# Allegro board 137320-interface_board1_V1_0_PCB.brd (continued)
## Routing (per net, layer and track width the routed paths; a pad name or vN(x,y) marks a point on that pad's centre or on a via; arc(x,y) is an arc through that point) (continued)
MAIN_UART_RX12: length 98.2
  TOP w0.152: R123.1 v1(117.98,30.48)
  ART03 w0.127: v1(117.98,30.48) 117.35,30.48 110.74,23.88 98.33,23.88 92.87,18.41 86.74,18.41 82.3,13.97 70.99,13.97 70.74,13.72 61.21,13.72 58.55,11.05 53.34,11.05 52.45,10.16 52.45,6.6 51.18,5.33 48.9,5.33 48,4.44 48,1.64 47.37,1.02 37.98,1.02 J4.15
MAIN_UART_RX13: length 130.6
  ART03 w0.127: J4.18 42.24,7.24 46.35,7.24 47.24,8.13 49.66,8.13 50.55,9.02 50.55,10.79 52.7,12.95 57.91,12.95 61.47,16.51 70.1,16.51 70.74,15.88 81.66,15.88 87.5,21.72 93.48,21.72 97.54,25.78 110.11,25.78 115.32,30.99 115.32,57.66 117.47,59.82 117.47,69.98 v1(117.98,70.48)
  BOTTOM w0.152: R128.1 v1(117.98,70.48)
MAIN_UART_RX14: length 108
  TOP w0.152: R133.1 v1(116.46,45.09)
  ART03 w0.127: J4.19 40,3 40,4.44 42.42,6.86 46.61,6.86 47.5,7.75 49.78,7.75 50.93,8.89 50.93,10.67 52.83,12.57 58.04,12.57 61.59,16.13 69.98,16.13 70.61,15.49 81.79,15.49 87.63,21.34 93.64,21.34 97.7,25.4 110.24,25.4 115.7,30.86 115.7,44.32 v1(116.46,45.09)
MAIN_UART_RX15: length 120.7
  TOP w0.152: R138.1 v1(117.98,59.69)
  ART03 w0.127: J4.21 42,3 42,4.41 43.69,6.1 50.8,6.1 51.69,6.99 51.69,10.41 53.09,11.81 58.29,11.81 60.96,14.48 70.23,14.48 70.48,14.73 82.04,14.73 86.49,19.18 92.56,19.18 98.02,24.64 110.49,24.64 116.46,30.61 116.46,35.18 116.97,35.69 116.97,58.67 v1(117.98,59.69)
MAIN_UART_RX16: length 91.4
  TOP w0.152: 108.58,40.77 v1(108.58,39.88)
  ART03 w0.127: v1(59.44,17.78) 59.69,18.03 67.31,18.03 71.75,22.48 80.52,22.48 85.34,27.3 90.81,27.3 91.19,27.69 106.3,27.69 108.58,29.97 v1(108.58,39.88)
  ART04 w0.127: v1(59.44,17.78) 60.07,17.14 60.07,9.65 56.39,5.97 53.59,5.97 52,4.37 52,3.61 51.39,3 50.62,3 50,2.37 50,1.49 49.53,1.02 47.98,1.02 J4.25
MAIN_UART_RX17: length 94.3
  TOP w0.152: R207.1 v1(107.31,55.75)
  ART03 w0.127: v1(107.31,55.75) 100.71,49.15 93.95,49.15 89.5,44.7 87.38,44.7 85.22,42.55 85.22,30.13 78.33,23.24 71.5,23.24 67.94,19.68 60.07,19.68 v1(58.17,17.78)
  ART04 w0.127: v1(58.17,17.78) 58.8,17.14 58.8,9.4 56.13,6.73 51.94,6.73 50.93,5.71 49.78,5.71 49,4.93 J4.28
MAIN_UART_RX18: length 82.2
  ART03 w0.127: J4.29 52,3 52,4.37 52.58,4.95 55.88,4.95 56.77,5.84 60.58,5.84 64.26,9.53 93.64,9.53 97.2,5.97 103.63,5.97 104.52,5.08 125.92,5.08 J6.30
MAIN_UART_RX19: length 80.8
  TOP w0.152: R40.1 v1(83.19,53.21)
  ART03 w0.127: J4.31 54,3 55.44,3 56,3.56 56,4.44 56.64,5.08 62.1,5.08 65.41,8.38 83.57,8.38 v1(83.69,8.26)
  ART04 w0.127: v1(83.69,8.26) 84.33,8.89 84.33,11.3 83.57,12.06 83.57,34.29 82.8,35.05 82.8,52.83 v1(83.19,53.21)
MAIN_UART_TX0_DEBUG: length 74.4
  TOP w0.152: v1(87.12,79.5) 87.12,75.69 90.81,72.01 90.81,65.91 87,62.1 84.71,62.1 83.86,61.25 U41.11
  ART03 w0.127: J3.20 43,87 43,85.65 44.2,84.45 60.23,84.45 64.67,80.01 86.61,80.01 v1(87.12,79.5)
MAIN_UART_TX1: length 56
  TOP w0.152: U11.5 v1(33.02,41.53)
  ART04 w0.127: J3.21 45,87 46.6,87 47,86.6 47,85.23 46.74,84.96 46.74,65.53 33.66,52.45 33.66,42.16 v1(33.02,41.53)
MAIN_UART_TX2: length 61.5
  TOP w0.152: U13.5 v1(43.18,41.53)
  ART04 w0.127: J3.24 46.49,88 47.5,87 54.48,87 55,86.48 55,85.35 53.91,84.27 53.91,72.46 50.87,69.41 50.87,59.76 42.55,51.44 42.55,42.16 v1(43.18,41.53)
MAIN_UART_TX3: length 50.1
  TOP w0.152: U15.5 v1(53.34,41.53)
  ART04 w0.127: v1(55.5,80.9) 55.5,72.01 52.7,69.22 52.7,42.16 v1(53.34,41.53)
  BOTTOM w0.152: v1(55.5,80.9) 53.85,82.55 53.09,82.55 50,85.64 J3.27
MAIN_UART_TX4: length 70.6
  TOP w0.152: U17.5 v1(33.02,25.65)
  ART04 w0.127: v1(33.02,25.65) 33.66,26.29 33.66,39.75 34.92,41.02 34.92,53.21 47.1,65.38 47.1,82.66 48.26,83.82 49.82,83.82 J3.29
MAIN_UART_TX5: length 67.2
  TOP w0.152: U19.5 v1(43.18,25.65)
  ART04 w0.127: v1(43.18,25.65) 43.81,26.29 43.81,52.2 51.22,59.61 51.22,69.26 54.27,72.31 54.27,83.1 56,84.83 J3.33
MAIN_UART_TX6: length 66.6
  TOP w0.152: U21.5 v1(53.34,25.65)
  ART04 w0.127: J3.36 59,87 59,80.59 55.88,77.47 55.88,71.88 53.98,69.98 53.98,26.29 v1(53.34,25.65)
MAIN_UART_TX7: length 104.2
  TOP w0.152: U23.5 v1(33.02,9.78)
  ART04 w0.127: v1(33.02,9.78) 33.66,9.14 42.29,9.14 43.94,10.79 50.55,10.79 52.32,9.02 54.86,9.02 55.24,9.4 55.24,60.83 58.17,63.75 58.17,70.48 60,72.32 J3.37
MAIN_UART_TX8: length 95
  TOP w0.152: v1(44.45,8.51) 43.18,9.78 U25.5
  ART04 w0.127: J3.39 60.58,84.58 60.58,72.39 59.05,70.87 59.05,58.17 56.9,56.01 56.9,9.53 55.63,8.26 44.7,8.26 v1(44.45,8.51)
MAIN_UART_TX9: length 32.8
  TOP w0.152: J4.6 28,3 29.54,3 30,3.46 30,4.35 30.86,5.21 49.91,5.21 53.98,9.27 53.98,10.16 53.34,10.79 U27.5
MAIN_UART_TX10: length 89.7
  TOP w0.152: U47.5 v1(113.67,9.91)
  ART03 w0.127: v1(59.18,8) 59.82,8.64 60.74,8.64 63.53,11.43 72.68,11.43 73.69,12.45 93.99,12.45 96.89,9.55 107.58,9.55 108.32,8.81 112.57,8.81 v1(113.67,9.91)
  BOTTOM w0.152: J4.10 31,4.33 32.51,5.84 57.02,5.84 v1(59.18,8)
MAIN_UART_TX11: length 100.1
  TOP w0.152: U49.5 v1(124.46,9.91)
  ART03 w0.127: v1(60.33,8) 60.64,8 63.69,11.05 72.84,11.05 73.85,12.06 93.91,12.06 96.75,9.22 107.45,9.22 108.31,8.36 122.91,8.36 v1(124.46,9.91)
  BOTTOM w0.152: J4.12 34.08,5.08 59.44,5.08 60.96,6.6 60.96,7.37 v1(60.33,8)
MAIN_UART_TX12: length 106.3
  TOP w0.152: U33.7 v1(124.33,26.67)
  ART03 w0.127: J4.13 36.36,0.64 49.15,0.64 50,1.49 50,4.53 50.42,4.95 51.44,4.95 52.83,6.35 52.83,10.03 53.47,10.67 58.67,10.67 61.34,13.34 70.99,13.34 71.25,13.59 82.42,13.59 86.87,18.03 92.96,18.03 98.42,23.5 121.41,23.5 124.33,26.42 v1(124.33,26.67)
MAIN_UART_TX13: length 146.1
  ART03 w0.127: J4.16 38.73,5.74 38.73,6.99 39.37,7.62 46.1,7.62 46.99,8.51 49.53,8.51 50.16,9.14 50.16,10.92 52.58,13.34 57.66,13.34 61.21,16.89 69.85,16.89 70.36,17.4 78.23,17.4 79.01,18.17 83.45,18.17 87.38,22.1 93.32,22.1 97.38,26.16 109.98,26.16 114.94,31.11 114.94,57.91 117.09,60.07 117.09,75.56 117.73,76.2 122.43,76.2 v1(124.33,74.3)
  BOTTOM w0.152: U35.7 v1(124.33,74.3)
MAIN_UART_TX14: length 108.4
  TOP w0.152: v1(116.46,36.2) 124.08,36.2 124.97,37.08 124.97,40.77 124.46,41.27 U37.7
  ART03 w0.127: J4.20 43.48,6.48 46.86,6.48 47.75,7.37 50.04,7.37 51.31,8.64 51.31,10.54 52.96,12.19 58.17,12.19 61.72,15.75 69.85,15.75 70.48,15.11 81.92,15.11 87.76,20.95 93.79,20.95 97.86,25.02 110.36,25.02 116.08,30.73 116.08,35.81 v1(116.46,36.2)
MAIN_UART_TX15: length 121
  TOP w0.152: U39.7 124.33,55.88 124.97,55.24 124.97,51.56 124.21,50.8 v1(117.98,50.8)
  ART03 w0.127: v1(117.98,50.8) 117.35,50.16 117.35,35.56 116.84,35.05 116.84,30.48 110.62,24.26 98.17,24.26 92.71,18.8 86.61,18.8 82.17,14.35 70.74,14.35 70.48,14.1 61.09,14.1 58.42,11.43 53.21,11.43 52.07,10.29 52.07,6.86 50.93,5.71 44.71,5.71 J4.22
MAIN_UART_TX16: length 87.6
  TOP w0.152: Q3.1 v1(110.8,33.66)
  ART03 w0.127: v1(59.44,16.51) 60.58,17.65 68.58,17.65 73.03,22.1 80.64,22.1 85.47,26.92 91.06,26.92 91.44,27.3 107.57,27.3 110.8,30.54 v1(110.8,33.66)
  ART04 w0.127: J4.23 46,3 49.35,3 50,3.64 50,4.79 50.55,5.33 51.05,5.33 52.07,6.35 56.26,6.35 59.44,9.53 v1(59.44,16.51)
  BOTTOM w0.152: R190.2 111.25,33.21 v1(110.8,33.66)
MAIN_UART_TX17: length 96.8
  TOP w0.152: Q7.1 v1(110.8,49.53)
  ART03 w0.127: v1(110.8,49.53) 110.04,48.77 94.11,48.77 89.66,44.32 87.5,44.32 85.6,42.42 85.6,29.97 78.49,22.86 71.63,22.86 67.18,18.41 59.31,18.41 58.8,17.91 58.8,17.14 v1(58.17,16.51)
  ART04 w0.127: v1(58.17,16.51) 58.17,9.27 56.01,7.11 51.82,7.11 50.8,6.1 49.1,6.1 J4.26
  BOTTOM w0.152: R198.2 111.25,49.08 v1(110.8,49.53)
MAIN_UART_TX18: length 84.6
  ART03 w0.127: J4.30 52.33,5.33 55.63,5.33 56.52,6.22 60.45,6.22 64.14,9.91 93.73,9.91 97.29,6.35 103.89,6.35 104.78,5.46 127,5.46 128,4.46 128,3 J6.29
MAIN_UART_TX19: length 65.5
  TOP w0.152: U6.52 82.26,46.74 82.01,46.48 v1(81.03,46.48)
  ART04 w0.127: v1(81.03,46.48) 79.76,45.21 79.76,29.21 80.39,28.57 80.39,24.51 77.47,21.59 77.47,13.97 72.26,8.76 65.28,8.76 61.85,5.33 54.33,5.33 J4.32
MAIN_USB_DN: length 68.9
  TOP w0.15: L8.2 19.28,66.95 19.55,66.69 19.55,21.59 21.44,19.7 21.44,14.33 21.21,14.1 21.21,13.74 21.44,13.5 21.44,13.14 21.21,12.9 21.21,12.54 21.44,12.31 21.44,11.94 21.21,11.71 21.21,11.34 21.44,11.11 21.44,10.74 21.21,10.51 21.21,10.14 21.44,9.91 21.44,9.54 21.21,9.31 21.21,8.94 21.44,8.71 21.44,8.34 21.21,8.11 21.21,7.74 21.44,7.51 21.44,7.14 21.21,6.91 21.21,6.54 21.44,6.31 21.44,5.94 21.21,5.71 21.21,5.34 21.44,5.11 21.44,4.74 21.21,4.51 21.21,4.14 21.44,3.91 21.44,3.56 J4.1
MAIN_USB_DP: length 68.8
  TOP w0.15: J4.3 24,3 22.39,3 21.72,3.67 21.72,19.81 19.82,21.71 19.82,66.69 20.09,66.95 L8.3
MAIN_USB_VBUS: length 99.1
  TOP w0.508: 54.36,66.67 53.34,66.67 47.88,72.14 35.94,72.14 34.92,71.12 26.54,71.12 23,67.58 J4.2
MAIN_USB_VBUS_EN_N: length 89.6
  ART04 w0.127: v1(57.15,60.33) 56.52,59.69 56.52,9.65 55.5,8.64 52.07,8.64 50.29,10.41 44.2,10.41 42.55,8.76 28.96,8.76 26,5.81 26,3 J4.5
  BOTTOM w0.152: R152.2 v1(57.15,60.33)
NC2: length 230.3
  TOP w0.152: v1(96.27,14.22) 91.69,18.8 84.96,18.8 v1(84.07,19.68) ; v1(39.37,15.24) 38.73,14.61 29.84,14.61 v1(29.21,15.24) ; U7.13 v1(134.62,14.22)
  ART03 w0.127: v1(96.27,14.22) 96.38,14.22 96.51,14.1 108.58,14.1 v1(109.86,12.83) 110.35,13.32 120.15,13.32 v1(120.65,12.83) 121.67,11.81 130.68,11.81 131.43,12.56 132.96,12.56 v1(134.62,14.22) ; v1(49.53,15.24) 50.16,15.88 59.69,15.88 61.09,17.27 69.72,17.27 70.98,18.53 82.92,18.53 v1(84.07,19.68) ; v1(49.53,44.45) v1(39.37,44.45)
  ART04 w0.127: v1(29.21,44.45) 30.73,42.93 30.73,39.62 29.84,38.73 29.84,29.21 v1(29.21,28.57) 30.61,27.18 30.61,23.75 29.84,22.99 29.84,15.88 v1(29.21,15.24) ; v1(39.37,15.24) 40.01,15.88 40.01,27.94 v1(39.37,28.57) 40.01,29.21 40.01,43.81 v1(39.37,44.45) ; v1(49.53,15.24) 50.16,15.88 50.16,27.94 v1(49.53,28.57) 50.16,29.21 50.16,43.81 v1(49.53,44.45)
  BOTTOM w0.152: 109.86,11.3 v1(109.86,12.83) ; U16.13 v1(49.53,44.45) ; U50.13 v1(120.65,12.83) ; U18.13 v1(29.21,28.57) ; U14.13 v1(39.37,44.45) ; U22.13 v1(49.53,28.57) ; U12.13 v1(29.21,44.45) ; U26.13 v1(39.37,15.24) ; U24.13 v1(29.21,15.24) ; U20.13 v1(39.37,28.57) ; U28.13 v1(49.53,15.24)
RS485_DRIVE_EN: length 88.1
  TOP w0.152: U7.4 v1(137.16,9.91) ; v1(87.12,41.53) 86.74,41.91 U6.40
  ART03 w0.127: v1(137.16,9.91) 135.28,8.03 108.17,8.03 107.31,8.89 99.44,8.89 v1(98.93,8.38)
  ART04 w0.127: v1(87.12,41.53) 84.96,39.37 84.96,14.48 90.81,8.64 98.68,8.64 v1(98.93,8.38)
  BOTTOM w0.152: v1(137.16,9.91) R49.1
RX_DEBUG_MAIN: length 77.5
  TOP w0.152: J1.41 10.99,66.09 12.64,64.45 D49.2 v1(15.88,64.45) ; v1(75.69,59.69) 75.96,59.95 U41.8
  ART03 w0.127: v1(75.69,59.69) 75.18,60.2 60.33,60.2 57.66,62.87 36.96,62.87 36.07,61.98 36.07,60.71 33.02,57.66 22.67,57.66 v1(15.88,64.45)
RX_DEBUG_SPARE: length 81.7
  TOP w0.152: U42.8 92.45,14.87 92.71,14.61 93.85,14.61 v1(94.23,14.22) ; D50.2 v1(144.15,24.45)
  ART03 w0.127: v1(144.15,24.45) 144.65,23.94 144.65,19.43 140.98,15.76 137.62,15.76 136.23,17.14 121.4,17.14 120.76,16.51 99.19,16.51 97.41,14.73 94.74,14.73 v1(94.23,14.22)
  ART04 w0.127: v1(144.15,24.45) 152.47,24.45 156.34,28.32 156.34,31.89 J2.43
SPARE_ID2: length 81
  TOP w0.152: v1(87.12,38.99) 86.55,38.41 U6.33
  ART03 w0.127: v1(114.3,40.01) 113.28,41.02 103.38,41.02 101.35,38.99 v1(87.12,38.99)
  ART04 w0.127: J5.12 111,87 111,83.69 114.3,80.39 v1(114.3,40.01)
  BOTTOM w0.152: R37.2 87,39.12 v1(87.12,38.99)
SPARE_POWER_EN: length 48.3
  TOP w0.152: 34.92,61.09 36.7,61.09 37.08,61.47 v1(37.08,61.98) ; v1(78.11,58.55) 78.36,58.29 Q2.3
  ART03 w0.127: v1(78.11,58.55) 75.69,58.55 75.18,59.05 70.23,59.05 69.47,59.82 60.07,59.82 57.91,61.98 v1(37.08,61.98)
  BOTTOM w0.152: v1(37.08,61.98) 37.59,61.98 37.74,62.12 U3.5
SPARE_SAFE_MODE_EN_N: length 305.8
  TOP w0.152: U36.6 v1(124.33,71.75)
  ART03 w0.127: v1(31.75,18.16) 32.13,18.16 32.77,17.53 41.27,17.53 v1(41.91,18.16) ; v1(62.1,12.32) 62.74,12.95 71.25,12.95 71.5,13.21 82.55,13.21 84.45,15.11 94.87,15.11 96.01,16.26 97.28,16.26 98.3,17.27 111.63,17.27 v1(112.39,18.03) 113.16,17.27 120.59,17.27 121.35,18.03 v1(123.19,18.03) ; v1(41.91,49.91) 42.42,49.4 51.56,49.4 v1(52.07,49.91)
  ART04 w0.127: v1(123.19,18.03) 125.35,20.19 125.35,28.19 v1(124.33,29.21) 124.97,29.84 124.97,43.18 v1(124.33,43.81) 124.97,44.45 124.97,57.78 v1(124.33,58.42) 123.7,59.05 123.7,71.12 v1(124.33,71.75) 125.09,72.52 125.09,78.61 v1(124.33,79.38) ; v1(31.75,18.16) 31.11,18.8 31.11,33.4 v1(31.75,34.04) 31.11,34.67 31.11,49.28 v1(31.75,49.91) ; v1(41.91,18.16) 41.27,18.8 41.27,33.4 v1(41.91,34.04) 41.27,34.67 41.27,49.28 v1(41.91,49.91) ; v1(52.07,49.91) 51.44,49.28 51.44,34.67 v1(52.07,34.04) 51.44,33.4 51.44,18.8 v1(52.07,18.16)
  BOTTOM w0.152: U40.6 v1(124.33,58.42) ; v1(62.1,12.32) 62.1,16.97 59.77,19.3 53.21,19.3 v1(52.07,18.16) U28.4 ; U48.4 v1(112.39,18.03) ; U14.4 v1(41.91,49.91) ; U20.4 v1(41.91,34.04) ; U22.4 v1(52.07,34.04) ; U12.4 v1(31.75,49.91) ; U18.4 v1(31.75,34.04) ; U26.4 v1(41.91,18.16) ; U38.6 v1(124.33,43.81) ; U50.4 v1(123.19,18.03) ; U34.6 v1(124.33,29.21) ; v1(124.33,79.38) 121.92,79.38 120.65,78.11 R2.2 119.89,82.3 117.86,84.33 116.14,84.33 115,85.47 115,87 J5.16 ; U16.4 v1(52.07,49.91) ; U24.4 v1(31.75,18.16)
SPARE_UART_RX0_DEBUG: length 81.2
  TOP w0.152: R149.1 v1(92.08,26.16)
  ART03 w0.127: v1(92.08,26.16) 96.39,26.16 97.16,26.92 109.47,26.92 113.79,31.24 113.79,32 v1(114.43,32.64)
  ART04 w0.127: J5.19 115.57,83.57 115.57,61.09 114.81,60.33 114.81,33.02 v1(114.43,32.64)
SPARE_UART_RX1: length 116.9
  ART03 w0.127: v1(29.21,52.83) 31.75,55.37 58.42,55.37 62.48,59.44 69.25,59.44 70.01,58.67 74.71,58.67 75.72,57.66 81.79,57.66 82.8,58.67 84.71,58.67 90.17,64.14 90.17,65.66 90.81,66.29 90.81,69.34 91.95,70.48 91.95,77.22 96.2,81.47 102.17,81.47 105.66,84.96 118.36,84.96 119,85.6 119,86.49 119.51,87 121,87 J5.23
  BOTTOM w0.152: R64.1 v1(29.21,52.83)
SPARE_UART_RX2: length 108.3
  ART03 w0.127: J5.26 123.06,87.06 123.06,85.47 121.89,84.3 106.02,84.3 102.53,80.81 96.48,80.81 92.71,77.04 92.71,65.66 83.95,56.9 75.15,56.9 74.39,57.66 61.72,57.66 57.91,53.85 40.39,53.85 v1(39.37,52.83)
  BOTTOM w0.152: R70.1 v1(39.37,52.83)
SPARE_UART_RX3: length 102.1
  ART03 w0.127: J5.28 127,87 127,84.96 125.35,83.31 106.55,83.31 102.74,79.5 102.74,74.17 84.33,55.75 74.68,55.75 73.91,56.52 62.1,56.52 54.86,49.28 53.09,49.28 52.7,49.66 52.7,50.16 51.31,51.56 50.8,51.56 v1(49.53,52.83)
  BOTTOM w0.152: R76.1 v1(49.53,52.83)
SPARE_UART_RX4: length 134.3
  ART03 w0.127: v1(29.21,36.96) 31.11,35.05 31.11,33.91 31.62,33.4 33.15,33.4 33.66,33.91 33.66,34.54 37.08,37.97 53.21,37.97 56.64,41.4 56.64,47.24 60.83,51.44 65.15,51.44 66.67,52.96 70.99,52.96 72.14,54.1 76.58,54.1 77.47,54.99 84.58,54.99 103.5,73.91 103.5,79.25 106.91,82.65 126.21,82.65 129,85.44 129,87 J5.30
  BOTTOM w0.152: R82.1 v1(29.21,36.96)
SPARE_UART_RX5: length 118.4
  ART03 w0.127: J5.31 130,85.93 126.39,82.32 107.09,82.32 103.89,79.12 103.89,73.79 84.71,54.61 77.6,54.61 76.71,53.72 72.26,53.72 71.12,52.58 66.8,52.58 65.28,51.05 61.09,51.05 57.02,46.99 57.02,41.15 53.47,37.59 40.01,37.59 v1(39.37,36.96)
  BOTTOM w0.152: R88.1 v1(39.37,36.96)
SPARE_UART_RX6: length 112.3
  ART03 w0.127: J5.34 131,87 131,85.6 130.36,84.96 129.54,84.96 126.57,81.99 107.26,81.99 104.27,78.99 104.27,73.66 84.84,54.23 77.72,54.23 76.83,53.34 72.39,53.34 71.25,52.2 66.93,52.2 65.41,50.67 61.21,50.67 57.4,46.86 57.4,41.02 52.83,36.45 50.04,36.45 v1(49.53,36.96)
  BOTTOM w0.152: R94.1 v1(49.53,36.96)
SPARE_UART_RX7: length 154.2
  ART03 w0.127: v1(29.21,21.08) 30.23,22.1 53.21,22.1 56.52,25.4 56.52,38.61 58.55,40.64 58.55,46.48 61.59,49.53 65.79,49.53 67.31,51.05 71.68,51.05 72.83,52.2 84.33,52.2 93.47,61.34 110.62,61.34 113.16,63.88 113.16,66.67 115.57,69.09 115.57,77.98 116.87,79.27 122.33,79.27 123.95,80.9 127,80.9 129.92,83.82 133.22,83.82 135,85.6 135,87 J5.38
  BOTTOM w0.152: R100.1 v1(29.21,21.08)
SPARE_UART_RX8: length 146.9
  ART03 w0.127: J5.40 137,87 137,85.56 134.49,83.06 130.18,83.06 127.25,80.14 124.21,80.14 122.68,78.61 117.22,78.61 116.33,77.72 116.33,68.83 113.92,66.42 113.92,63.63 110.87,60.58 93.73,60.58 84.58,51.44 73.28,51.44 71.37,49.53 67.44,49.53 66.67,48.77 61.85,48.77 59.31,46.23 59.31,40.39 57.28,38.35 57.28,25.15 52.2,20.07 40.39,20.07 v1(39.37,21.08)
  BOTTOM w0.152: R106.1 v1(39.37,21.08)
SPARE_UART_RX9: length 71.6
  ART03 w0.127: v1(62.61,6.99) 64.77,9.14 93.56,9.14 97.11,5.59 103.41,5.59 J6.8
  BOTTOM w0.152: R112.1 50.16,20.83 50.16,21.34 50.55,21.72 58.17,21.72 62.61,17.27 v1(62.61,6.99)
SPARE_UART_RX10: length 22
  ART04 w0.127: J6.9 106,3 106,9.48 109.22,12.7 109.22,20.45 v1(109.86,21.08)
  BOTTOM w0.152: R168.1 v1(109.86,21.08)
SPARE_UART_RX11: length 25.5
  BOTTOM w0.152: J6.11 110,3 110,4.72 113.28,8 116.84,8 117.35,8.51 117.35,17.53 120.02,20.19 R173.1
SPARE_UART_RX12: length 28.8
  TOP w0.152: v1(116.84,8.89) 116.2,8.26 116.2,5.71 116,5.51 116,3.48 115.52,3 114,3 J6.15
  ART04 w0.127: v1(116.84,8.89) 117.86,9.91 117.86,20.7 117.47,21.08 117.47,26.16 v1(117.98,26.67)
  BOTTOM w0.152: R126.1 v1(117.98,26.67)
SPARE_UART_RX13: length 73.8
  TOP w0.152: J6.18 115,8.07 v1(115.82,8.89) ; R131.1 v1(117.98,74.3)
  ART04 w0.127: v1(117.98,74.3) 117.22,73.53 117.22,61.72 115.57,60.07 115.57,35.81 116.33,35.05 116.33,20.61 116.71,20.23 116.71,11.68 115.32,10.29 115.32,9.4 v1(115.82,8.89)
SPARE_UART_RX14: length 41.8
  TOP w0.152: v1(116.84,9.91) 117.35,9.4 117.35,7.49 118,6.84 118,3 J6.19
  ART04 w0.127: v1(117.98,41.27) 117.09,40.39 117.09,20.92 117.47,20.54 117.47,10.54 v1(116.84,9.91)
  BOTTOM w0.152: R136.1 v1(117.98,41.27)
SPARE_UART_RX15: length 66.3
  TOP w0.152: J6.21 118.02,1.02 112.52,1.02 112,1.54 112,4.56 113.67,6.22 113.67,7.75 v1(115.82,9.91)
  ART04 w0.127: v1(115.82,9.91) 115.82,10.16 117.09,11.43 117.09,20.39 116.71,20.77 116.71,35.18 115.95,35.94 115.95,53.85 v1(117.98,55.88)
  BOTTOM w0.152: R141.1 v1(117.98,55.88)
SPARE_UART_RX16: length 48.7
  TOP w0.152: 107.31,40.77 v1(107.31,39.88)
  ART04 w0.127: v1(107.31,39.88) 107.31,38.61 108.46,37.47 108.46,30.48 111.76,27.18 111.76,9.27 v1(114.3,6.73)
  BOTTOM w0.152: v1(114.3,6.73) 115.57,5.46 121.41,5.46 122,4.87 122,3 J6.25
SPARE_UART_RX17: length 65.3
  TOP w0.152: R206.1 v1(108.58,55.75)
  ART04 w0.127: v1(108.58,55.75) 112.27,55.75 113.67,54.36 113.67,39.62 113.92,39.37 113.92,22.48 115.57,20.83 115.57,11.43 114.94,10.79 114.94,8.64 v1(116.84,6.73)
  BOTTOM w0.152: J6.28 122.78,6.22 117.35,6.22 v1(116.84,6.73)
SPARE_UART_RX19: length 115.4
  TOP w0.152: v1(81.03,49.15) 80.76,48.88 U6.55 ; J9.5 v1(80.01,67.06)
  ART03 w0.127: v1(82.42,10.41) 82.93,10.92 93.65,10.92 97.46,7.11 104.39,7.11 105.28,6.22 128.14,6.22 130,4.37 130,3 J6.31
  ART04 w0.127: v1(80.01,67.06) 80.01,50.16 v1(81.03,49.15) 81.66,48.51 81.66,45.59 81.03,44.96 81.03,29.46 81.79,28.7 81.79,11.05 v1(82.42,10.41)
SPARE_UART_TX0_DEBUG: length 87.1
  TOP w0.152: U42.11 v1(91.15,22.61)
  ART03 w0.127: v1(91.15,22.61) 93.34,22.61 97.28,26.54 109.6,26.54 v1(114.43,31.37)
  ART04 w0.127: v1(114.43,31.37) 115.19,32.13 115.19,60.2 116.84,61.85 116.84,83.19 119,85.35 119,87 J5.20
SPARE_UART_TX1: length 111.6
  ART03 w0.127: v1(33.02,49.91) 37.34,54.23 57.78,54.23 62.61,59.05 69.09,59.05 69.85,58.29 74.55,58.29 75.56,57.28 83.82,57.28 90.55,64.01 90.55,65.53 92.33,67.31 92.33,77.13 96.34,81.14 102.35,81.14 105.84,84.63 118.63,84.63 J5.21
  BOTTOM w0.152: U12.5 v1(33.02,49.91)
SPARE_UART_TX2: length 112
  ART03 w0.127: v1(43.18,49.91) 46.74,53.47 58.04,53.47 61.85,57.28 74.23,57.28 74.99,56.52 84.07,56.52 93.09,65.53 93.09,76.96 96.61,80.48 102.7,80.48 106.2,83.97 123.6,83.97 124.97,85.34 124.97,88.39 124.33,89.03 123.03,89.03 J5.24
  BOTTOM w0.152: U14.5 v1(43.18,49.91)
SPARE_UART_TX3: length 93.5
  ART03 w0.127: v1(53.34,49.91) 56.52,53.09 58.17,53.09 61.98,56.9 74.07,56.9 74.83,56.13 84.2,56.13 102.36,74.3 102.36,79.63 106.38,83.64 124.66,83.64 126,84.98 J5.27
  BOTTOM w0.152: U16.5 v1(53.34,49.91)
SPARE_UART_TX4: length 125.8
  ART03 w0.127: v1(33.02,34.04) 33.02,34.92 37.34,39.24 53.21,39.24 55.24,41.27 55.24,47.24 59.82,51.82 65.02,51.82 66.55,53.34 69.98,53.34 72.01,55.37 84.45,55.37 103.12,74.04 103.12,79.38 106.73,82.98 126.03,82.98 128,84.95 J5.29
  BOTTOM w0.152: U18.5 v1(33.02,34.04)
SPARE_UART_TX5: length 118.4
  ART03 w0.127: J5.33 130.58,84.58 129.67,84.58 126.75,81.66 107.44,81.66 104.65,78.87 104.65,73.53 84.96,53.85 77.85,53.85 76.96,52.96 72.52,52.96 71.37,51.82 67.06,51.82 65.53,50.29 61.34,50.29 57.78,46.74 57.78,40.89 51.82,34.92 44.07,34.92 v1(43.18,34.04)
  BOTTOM w0.152: U20.5 v1(43.18,34.04)
SPARE_UART_TX6: length 116.7
  ART03 w0.127: J5.36 133,87 133,85.6 131.6,84.2 129.79,84.2 126.87,81.28 123.83,81.28 122.15,79.6 116.69,79.6 115.19,78.11 115.19,69.22 112.78,66.8 112.78,64.01 110.49,61.72 93.34,61.72 84.2,52.58 72.64,52.58 71.5,51.44 67.18,51.44 65.66,49.91 61.47,49.91 58.17,46.61 58.17,40.77 53.34,35.94 v1(53.34,34.04)
  BOTTOM w0.152: U22.5 v1(53.34,34.04)
SPARE_UART_TX7: length 151.1
  ART03 w0.127: J5.37 133.44,83.44 130.05,83.44 127.13,80.52 124.08,80.52 122.5,78.94 117.04,78.94 115.95,77.85 115.95,68.96 113.54,66.55 113.54,63.75 110.74,60.96 93.6,60.96 84.45,51.82 73.08,51.82 71.93,50.67 67.44,50.67 65.91,49.15 61.72,49.15 58.93,46.35 58.93,40.51 56.9,38.48 56.9,25.27 53.34,21.72 35.81,21.72 33.02,18.92 v1(33.02,18.16)
  BOTTOM w0.152: U24.5 v1(33.02,18.16)
SPARE_UART_TX8: length 141.9
  ART03 w0.127: v1(43.18,18.16) 44.58,19.56 52.2,19.56 57.66,25.02 57.66,38.23 59.69,40.26 59.69,46.1 61.98,48.39 70.74,48.39 73.41,51.05 84.71,51.05 93.85,60.2 111,60.2 114.3,63.5 114.3,66.29 116.71,68.71 116.71,76.58 117.6,77.47 122.05,77.47 123.32,78.74 126.36,78.74 130.3,82.68 134.68,82.68 J5.39
  BOTTOM w0.152: U26.5 v1(43.18,18.16)
SPARE_UART_TX9: length 66.4
  ART03 w0.127: v1(61.47,5.84) 62.36,5.84 65.28,8.76 93.47,8.76 97.03,5.21 101.79,5.21 J6.6
  BOTTOM w0.152: U28.5 53.34,18.03 54.1,18.8 59.56,18.8 61.47,16.89 v1(61.47,5.84)
SPARE_UART_TX10: length 22.8
  ART04 w0.127: v1(113.67,18.03) 113.03,17.4 113.03,8.76 114.81,6.99 114.81,6.48 114.43,6.1 109.1,6.1 J6.10
  BOTTOM w0.152: U48.5 v1(113.67,18.03)
SPARE_UART_TX11: length 27.6
  ART04 w0.127: v1(124.46,18.03) 123.83,17.4 123.83,9.4 121.79,7.37 118.49,7.37 118.11,6.99 118.11,6.6 117.22,5.71 116.33,5.71 115.95,5.33 110.33,5.33 J6.12
  BOTTOM w0.152: U50.5 v1(124.46,18.03)
SPARE_UART_TX12: length 43.1
  ART04 w0.127: J6.13 112.05,3.05 115.44,3.05 116,3.61 116,4.37 116.59,4.95 117.47,4.95 118.24,5.71 122.43,5.71 126.24,9.53 126.24,30.23 v1(125.98,30.48)
  BOTTOM w0.152: U34.7 v1(125.98,30.48)
SPARE_UART_TX13: length 78.1
  TOP w0.152: U36.7 v1(124.33,70.48)
  ART04 w0.127: v1(124.33,70.48) 125.35,69.47 125.35,29.84 125.73,29.46 125.73,19.94 125.09,19.3 125.09,8.89 122.3,6.1 118.11,6.1 117.35,5.33 116.46,5.33 116.08,4.95 113.95,4.95 J6.16
SPARE_UART_TX14: length 51
  ART04 w0.127: J6.20 118.33,5.33 122.56,5.33 126.62,9.4 126.62,44.45 v1(125.98,45.09)
  BOTTOM w0.152: U38.7 v1(125.98,45.09)
SPARE_UART_TX15: length 64.5
  ART04 w0.127: v1(125.98,59.69) 125.98,46.1 127,45.09 127,8.76 123.19,4.95 119.95,4.95 J6.22
  BOTTOM w0.152: U40.7 v1(125.98,59.69)
SPARE_UART_TX16: length 42.2
  TOP w0.152: Q5.1 v1(107.63,33.66)
  ART04 w0.127: v1(107.63,33.66) 107.63,30.42 110.49,27.56 110.49,9.27 v1(113.03,6.73)
  BOTTOM w0.152: J6.23 120,3 120,4.71 119.63,5.08 114.68,5.08 v1(113.03,6.73) ; R191.2 108.08,33.21 v1(107.63,33.66)
SPARE_UART_TX17: length 58.2
  TOP w0.152: Q9.1 v1(107.63,49.53)
  ART04 w0.127: v1(107.63,49.53) 108.77,48.39 110.11,48.39 113.28,45.21 113.28,39.5 113.54,39.24 113.54,22.23 114.3,21.46 114.3,8.03 v1(115.59,6.75)
  BOTTOM w0.152: J6.26 123,5.21 122.37,5.84 116.49,5.84 v1(115.59,6.75) ; v1(107.63,49.53) 108.08,49.08 R199.2
SPARE_UART_TX19: length 121.2
  TOP w0.152: U6.56 80.26,49.65 v1(81.03,50.42) ; J9.8 v1(82.55,76.33)
  ART03 w0.127: J6.32 127.16,5.84 105.03,5.84 104.14,6.73 97.37,6.73 93.69,10.41 v1(83.69,10.41)
  ART04 w0.127: v1(82.55,76.33) 80.9,74.68 80.9,54.23 81.28,53.85 81.28,50.67 v1(81.03,50.42) 82.3,49.15 82.3,11.81 v1(83.69,10.41)
SPARE_USB_DN: length 71.6
  BOTTOM w0.15: J6.1 98.29,1.29 97.89,1.29 97.28,1.91 97.28,2.9 97.43,3.05 97.51,3.05 97.66,3.2 97.66,3.5 97.51,3.65 97.43,3.65 97.28,3.8 97.28,4.43 97.76,4.91 98,4.91 98.3,5.21 98.3,5.45 99.07,6.22 99.61,6.22 99.86,5.97 100.21,5.97 100.46,6.22 100.81,6.22 101.06,5.97 101.41,5.97 101.66,6.22 102.01,6.22 102.26,5.97 102.61,5.97 102.86,6.22 103.64,6.22 104.07,6.66 104.29,6.66 104.32,6.62 104.54,6.62 104.75,6.83 104.75,7.04 104.71,7.08 104.71,7.29 104.92,7.5 105.13,7.5 105.17,7.47 105.38,7.47 105.6,7.68 105.6,7.89 105.56,7.93 105.56,8.14 105.77,8.35 105.98,8.35 106.02,8.31 106.23,8.31 106.44,8.53 106.44,8.74 106.41,8.77 106.41,8.99 106.62,9.2 106.83,9.2 106.87,9.16 107.08,9.16 107.29,9.37 107.29,9.59 107.25,9.62 107.25,9.83 107.72,10.3 107.72,21.09 108.34,21.72 123.94,21.72 126.12,19.54 139.43,19.54 142.51,22.61 142.51,24.9 142.77,25.17 L9.2
SPARE_USB_DP: length 71.6
  BOTTOM w0.15: J6.3 100.02,1.02 97.78,1.02 97.01,1.79 97.01,4.55 98.96,6.5 103.53,6.5 107.44,10.41 107.44,21.21 108.23,21.99 124.06,21.99 126.24,19.81 139.32,19.81 142.23,22.72 142.23,24.9 141.97,25.17 L9.3
SPARE_USB_VBUS: length 18.1
  ART04 w0.508: J6.2 99,5.4 101.85,8.26 101.85,12.32 99.69,14.48 v1(99.69,20.07)
SPARE_USB_VBUS_EN_N: length 15.2
  ART04 w0.127: v1(100.97,14.61) 102.49,13.08 102.49,9.65 104,8.14 104,3 J6.5
  BOTTOM w0.152: R155.2 v1(100.97,14.61)
SPI_CS_N: length 25.1
  TOP w0.152: R28.1 v1(75.31,31.24) ; v1(60.58,20.32) 61.57,21.31 U8.2
  ART03 w0.127: v1(60.58,20.32) 59.94,20.95 59.94,22.26 64.74,27.05 71.12,27.05 v1(75.31,31.24)
SPI_MISO: length 17.1
  TOP w0.152: R33.1 v1(77.85,31.24) ; v1(67.56,21.59) 67.84,21.31 68.96,21.31
  ART03 w0.127: v1(67.56,21.59) 68.83,21.59 77.85,30.61 v1(77.85,31.24)
SPI_MOSI: length 21.2
  TOP w0.152: 68.96,21.96 68.07,21.96 67.93,22.1 66.8,22.1 v1(66.29,21.59) ; R34.1 v1(79.12,31.24)
  ART03 w0.127: v1(66.29,21.59) 66.93,20.95 68.71,20.95 78.99,31.24 v1(79.12,31.24)
SPI_SCK: length 24.5
  TOP w0.152: v1(60.58,21.59) 60.95,21.96 U8.1 ; R29.1 v1(76.58,31.24)
  ART03 w0.127: v1(60.58,21.59) 60.58,22.35 64.9,26.67 72.77,26.67 76.58,30.48 v1(76.58,31.24)
TCK_MON: length 32
  TOP w0.152: v1(83.82,49.15) 83.76,49.09 U6.49 ; J9.10 v1(85.09,76.33)
  ART04 w0.127: v1(83.82,49.15) 84.45,49.78 84.45,53.59 83.82,54.23 83.82,67.31 85.09,68.58 v1(85.09,76.33)
TDI_MON: length 22.5
  TOP w0.152: J9.7 v1(82.55,67.06) ; v1(83.82,50.42) 83.26,49.86 U6.50
  ART04 w0.127: v1(82.55,67.06) 82.55,54.86 83.82,53.59 v1(83.82,50.42)
TMS_MON: length 28.3
  TOP w0.152: v1(88.39,45.59) 87.71,44.91 U6.46 ; J9.9 v1(85.09,67.06)
  ART04 w0.127: v1(88.39,45.59) 85.09,48.9 v1(85.09,67.06)
TX_DEBUG_MAIN: length 86.5
  TOP w0.152: v1(15.88,66.36) D49.1 12.89,66.36 10.74,68.51 J1.42 ; v1(79.5,61.59) 80.14,62.23 81.79,62.23 82.11,62.56 U41.13
  ART03 w0.127: v1(79.5,61.59) 69.6,61.59 68.58,60.58 60.58,60.58 57.78,63.37 40.89,63.37 40.64,63.63 35.94,63.63 35.56,63.25 35.56,60.83 32.77,58.04 22.86,58.04 16.51,64.39 16.51,65.73 v1(15.88,66.36)
TX_DEBUG_SPARE: length 83.2
  TOP w0.152: v1(96.27,15.62) 92.46,19.43 90.81,19.43 89.84,20.39 U42.13 ; D50.1 v1(144.15,22.54)
  ART03 w0.127: v1(144.15,22.54) 144.15,19.43 140.8,16.09 137.76,16.09 136.33,17.51 121.3,17.51 120.67,16.89 98.93,16.89 97.66,15.62 v1(96.27,15.62)
  ART04 w0.127: J2.44 155.96,29.99 155.96,28.48 152.62,25.15 143.89,25.15 143.51,24.77 143.51,23.17 v1(144.15,22.54)
UART1_RXD: length 85.1
  TOP w0.152: U6.43 87.78,43.41 v1(88.39,42.8)
  ART03 w0.127: v1(134.62,12.83) 134.02,12.23 131.61,12.23 130.81,11.43 121.41,11.43 120.54,12.31 109.61,12.31 108.2,13.72 95.76,13.72 v1(95.25,14.22)
  ART04 w0.127: v1(95.25,14.22) 94.36,13.34 87.12,13.34 85.72,14.73 85.72,35.81 88.9,38.99 88.9,42.29 v1(88.39,42.8)
  BOTTOM w0.152: R46.1 v1(134.62,12.83)
UART1_TXD: length 90.5
  TOP w0.152: U7.5 v1(138.43,9.91)
  ART03 w0.127: v1(100.2,8.38) 107.35,8.38 108.04,7.7 136.22,7.7 v1(138.43,9.91)
  ART04 w0.127: v1(100.2,8.38) 99.57,9.02 90.93,9.02 85.34,14.61 85.34,36.07 88.39,39.12 v1(88.39,41.53)
  BOTTOM w0.152: v1(88.39,41.53) 87.76,42.16 85.34,42.16 85.09,42.42 R36.2
VISO_MAIN: length 21.7
  TOP w0.381: U39.12 C183.1 C184.1 135.38,54.99 135.65,55.26 137.43,55.26 138.05,55.88 138.05,62.48 137.67,62.87 136.14,62.87 C181.1 135.51,63.5 v1(134.37,63.5) 133.1,62.23 U39.19
  BOTTOM w0.381: C182.1 v1(134.37,63.5)
VISO_MAIN_2407607: length 21.7
  TOP w0.381: U33.12 C135.1 C134.1 135.38,25.78 135.65,26.05 137.43,26.05 138.05,26.67 138.05,33.27 137.67,33.66 136.14,33.66 135.51,34.29 v1(134.37,34.29) 133.1,33.02 U33.19
  BOTTOM w0.381: C136.1 v1(134.37,34.29)
VISO_MAIN_2410539: length 23
  BOTTOM w0.381: U35.12 C152.1 135.38,75.69 C149.1 136.14,74.93 137.67,74.93 138.05,74.55 138.05,66.42 137.54,65.91 135.64,65.91 135.38,66.17 C151.1 C150.1 U35.19
VISO_MAIN_2413471: length 21.7
  TOP w0.381: U37.19 133.1,47.62 v1(134.37,48.9) 135.51,48.9 C165.1 136.14,48.26 137.67,48.26 138.05,47.88 138.05,41.27 137.43,40.66 135.65,40.66 135.38,40.39 C168.1 C167.1 U37.12
  BOTTOM w0.381: C166.1 v1(134.37,48.9)
VISO_SPARE: length 23
  BOTTOM w0.381: U40.19 C190.1 C191.1 135.38,51.56 135.64,51.31 137.54,51.31 138.05,51.82 138.05,59.94 137.67,60.33 136.14,60.33 C189.1 135.38,61.09 C192.1 U40.12
VISO_SPARE_2408361: length 23
  BOTTOM w0.381: U34.12 C142.1 135.38,31.88 C141.1 136.14,31.11 137.67,31.11 138.05,30.73 138.05,22.61 137.54,22.1 135.64,22.1 135.38,22.35 C143.1 C144.1 U34.19
VISO_SPARE_2411293: length 21.7
  TOP w0.381: U36.12 C159.1 C160.1 135.38,69.6 135.65,69.87 137.43,69.87 138.05,70.48 138.05,77.09 137.67,77.47 136.14,77.47 C157.1 135.51,78.11 v1(134.37,78.11) 133.1,76.83 U36.19
  BOTTOM w0.381: C158.1 v1(134.37,78.11)
VISO_SPARE_2414225: length 23
  BOTTOM w0.381: U38.19 C174.1 C175.1 135.38,36.96 135.64,36.7 137.54,36.7 138.05,37.21 138.05,45.34 137.67,45.72 136.14,45.72 C173.1 135.38,46.48 C176.1 U38.12
Y1: length 43.6
  TOP w0.254: J1.39 6.11,60 6.11,58.16 6.61,57.65 8.04,57.65 9.25,58.86 11.25,58.86 13.27,56.83 D19.2 v1(15.88,56.83) ; U11.9 v1(34.29,46.99)
  ART03 w0.254: v1(34.29,46.99) 32.38,48.9 32.38,50.29 31.5,51.18 25.78,51.18 20.13,56.83 v1(15.88,56.83)
  BOTTOM w0.254: U12.9 v1(34.29,46.99)
Y2: length 52.2
  TOP w0.254: U13.9 v1(44.45,46.99)
  ART03 w0.254: v1(44.45,46.99) 43.43,48.01 39.88,48.01 38.25,46.38 27.53,46.38 20.7,53.21 15.49,53.21 13.72,54.99 v1(13.72,55.57)
  BOTTOM w0.254: J1.58 7.88,57.65 9.14,56.39 10.92,56.39 11.74,55.57 v1(13.72,55.57) D21.2 ; U14.9 v1(44.45,46.99)
Y3: length 60.7
  TOP w0.254: U15.9 v1(54.61,46.99)
  ART03 w0.254: v1(54.61,46.99) 53.47,48.13 50.41,48.13 49.71,47.43 49.71,46.55 50.16,46.09 50.16,44.2 49.76,43.79 27.08,43.79 20.7,50.16 15.24,50.16 13.72,51.69 v1(13.72,52.39)
  BOTTOM w0.254: U16.9 v1(54.61,46.99) ; D23.2 v1(13.72,52.39) 11.9,52.39 J1.13
Y4: length 46.1
  TOP w0.254: U17.9 v1(34.29,31.11)
  ART03 w0.254: v1(34.29,31.11) 32.82,32.59 28.24,32.59 19.48,41.35 17.46,41.35 16.97,41.85 16.97,43.12 16.32,43.76 15.29,43.76 14.35,44.7 14.35,48.58 v1(13.72,49.22)
  BOTTOM w0.254: J1.34 7.38,48.66 9.18,46.86 11.36,46.86 v1(13.72,49.22) D25.2 ; U18.9 v1(34.29,31.11)
Y5: length 55.5
  TOP w0.254: U19.9 v1(44.45,31.11)
  ART03 w0.254: v1(13.72,42.87) 14.35,42.23 14.35,40.51 15.88,38.99 18.8,38.99 27.28,30.51 38.51,30.51 40.13,32.13 43.43,32.13 v1(44.45,31.11)
  BOTTOM w0.254: U20.9 v1(44.45,31.11) ; J1.53 4.84,45.04 6.71,43.17 8.04,43.17 9.25,41.96 11.61,41.96 12.51,42.87 v1(13.72,42.87) D27.2
Y6: length 58.1
  TOP w0.254: U21.9 v1(54.61,31.11)
  ART03 w0.254: v1(13.72,37.79) 13.72,36.96 15.16,35.51 19.23,35.51 26.72,28.02 44.64,28.02 48.83,32.21 53.52,32.21 v1(54.61,31.11)
  BOTTOM w0.254: J1.8 10.48,37.79 v1(13.72,37.79) D29.2 ; U22.9 v1(54.61,31.11)
Y7: length 47.3
  TOP w0.254: U23.9 v1(34.29,15.24)
  ART03 w0.254: v1(13.72,34.61) 13.72,34.04 15.49,32.26 19.43,32.26 21.84,29.84 21.84,22.61 26.92,17.53 32,17.53 v1(34.29,15.24)
  BOTTOM w0.254: U24.9 v1(34.29,15.24) ; D31.2 v1(13.72,34.61) 11.56,34.61 11.44,34.73 9.25,34.73 7.38,36.6 J1.29
Y8: length 59.8
  TOP w0.254: U25.9 v1(44.45,15.24)
  ART03 w0.254: v1(13.72,31.44) 13.72,30.35 15.37,28.7 17.65,28.7 19.81,26.54 19.81,21.59 26.72,14.68 37.02,14.68 38.34,16 43.69,16 v1(44.45,15.24)
  BOTTOM w0.254: J1.48 4.84,32.98 6.71,31.11 8.01,31.11 9.14,29.97 10.79,29.97 12.26,31.44 v1(13.72,31.44) D33.2 ; U26.9 v1(44.45,15.24)
Y9: length 61
  TOP w0.254: U27.9 v1(54.61,15.24)
  ART03 w0.254: v1(54.61,15.24) 53.1,13.73 51.52,13.73 51.05,13.26 45.14,13.26 43.36,11.48 24.59,11.48 13.08,22.99 13.08,24.45 v1(13.72,25.09)
  BOTTOM w0.254: J1.3 11.11,25.09 v1(13.72,25.09) D35.2 ; U28.9 v1(54.61,15.24)
Y10: length 66.9
  TOP w0.254: D51.2 v1(143.51,38.41) 148.58,38.41 J2.10 ; v1(114.94,15.24) U47.9
  ART03 w0.254: v1(114.94,15.24) 120.05,15.24 121.45,16.64 136.14,16.64 137.41,15.37 141.22,15.37 145.16,19.3 145.16,25.02 144.91,25.27 144.91,37.02 v1(143.51,38.41)
  BOTTOM w0.254: U48.9 114.94,11.94 114.3,12.57 114.3,14.61 v1(114.94,15.24)
Y11: length 124.2
  TOP w0.254: D54.2 v1(143.51,51.11) 147.08,51.11 147.32,51.35 J2.5 ; v1(129.54,18.03) 129.41,18.03 125.35,22.1 115.57,22.1 113.67,24 113.67,38.35 108.71,43.31 102.23,43.31 101.24,42.31 R193.2
  ART03 w0.254: v1(143.51,51.11) 144.59,51.11 147.47,48.23 147.47,18.57 140.74,11.84 131.93,11.84 131.01,10.92 129.29,10.92 v1(128.27,9.91)
  ART04 w0.254: v1(129.54,18.03) 128.91,17.4 128.91,10.54 v1(128.27,9.91)
  BOTTOM w0.254: R211.2 128.27,10.05 v1(128.27,9.91)
Y_SWITCH: length 26.4
  TOP w0.254: J2.12 149.98,35.25 D16.2 v1(144.15,35.25) ; U7.9 v1(139.7,18.03)
  ART03 w0.254: v1(139.7,18.03) 141.99,20.32 141.99,27.18 143,28.19 143,34.1 v1(144.15,35.25)
Z1: length 41.3
  TOP w0.254: v1(15.88,58.74) D19.1 13.4,58.74 10.87,61.27 9.25,61.27 7.38,59.4 J1.38 ; U11.10 v1(33.02,46.99)
  ART03 w0.254: v1(15.88,58.74) 15.11,57.98 15.11,56.52 15.62,56.01 20.19,56.01 25.53,50.67 30.61,50.67 31.11,50.16 31.11,48.9 v1(33.02,46.99)
  BOTTOM w0.254: U12.10 v1(33.02,46.99)
Z2: length 49.5
  TOP w0.254: U13.10 v1(43.18,46.99)
  ART03 w0.254: v1(43.18,46.99) 42.62,47.55 40.07,47.55 38.44,45.92 27.23,45.92 20.4,52.76 15.3,52.76 14.41,53.65 v1(13.72,53.65)
  BOTTOM w0.254: D21.1 v1(13.72,53.65) 11.88,53.65 11.5,54.03 9.25,54.03 8.04,55.24 J1.57 ; U14.10 v1(43.18,46.99)
Z3: length 58.5
  TOP w0.254: U15.10 v1(53.34,46.99)
  ART03 w0.254: v1(53.34,46.99) 52.7,47.62 50.55,47.62 50.16,47.24 50.16,46.74 50.67,46.23 50.67,43.94 50.06,43.33 26.77,43.33 20.45,49.66 14.54,49.66 v1(13.72,50.48)
  BOTTOM w0.254: J1.12 12.4,50.48 v1(13.72,50.48) D23.1 ; U16.10 v1(53.34,46.99)
Z4: length 43.7
  TOP w0.254: U17.10 v1(33.02,31.11)
  ART03 w0.254: v1(13.72,47.3) 13.72,44.58 14.99,43.31 16.13,43.31 16.51,42.93 16.51,41.66 17.27,40.89 19.18,40.89 27.94,32.13 32,32.13 v1(33.02,31.11)
  BOTTOM w0.254: U18.10 v1(33.02,31.11) ; J1.33 7.38,46.25 9.25,44.38 10.79,44.38 v1(13.72,47.3) D25.1
Z5: length 53.1
  TOP w0.254: U19.10 v1(43.18,31.11)
  ART03 w0.254: v1(13.72,40.95) 13.72,40.13 15.37,38.48 18.54,38.48 26.97,30.05 38.7,30.05 40.32,31.67 42.62,31.67 v1(43.18,31.11)
  BOTTOM w0.254: D27.1 v1(13.72,40.95) 12.76,40.95 11.36,39.55 9.25,39.55 8.04,40.76 6.71,40.76 4.84,42.63 J1.52 ; U20.10 v1(43.18,31.11)
Z6: length 55.3
  TOP w0.254: U21.10 v1(53.34,31.11)
  ART03 w0.254: v1(13.72,35.87) 14.54,35.05 18.92,35.05 26.42,27.56 44.83,27.56 49.02,31.75 52.7,31.75 v1(53.34,31.11)
  BOTTOM w0.254: U22.10 v1(53.34,31.11) ; D29.1 v1(13.72,35.87) 9.97,35.87 J1.7
Z7: length 45
  TOP w0.254: U23.10 v1(33.02,15.24)
  ART03 w0.254: v1(13.72,32.7) 14.62,31.8 19.13,31.8 21.34,29.59 21.34,22.35 26.67,17.02 31.24,17.02 v1(33.02,15.24)
  BOTTOM w0.254: D31.1 v1(13.72,32.7) 11.56,32.7 11.17,32.31 9.25,32.31 7.38,34.19 J1.28 ; U24.10 v1(33.02,15.24)
Z8: length 57.9
  TOP w0.254: U25.10 v1(43.18,15.24)
  ART03 w0.254: v1(13.72,29.52) 13.72,27.05 15.11,25.65 16,25.65 17.02,24.64 17.02,22.1 25.81,13.31 41.25,13.31 v1(43.18,15.24)
  BOTTOM w0.254: D33.1 v1(13.72,29.52) 13.27,29.52 11.23,27.49 9.25,27.49 8.04,28.69 6.71,28.69 4.84,30.57 J1.47 ; U26.10 v1(43.18,15.24)
Z9: length 56.2
  TOP w0.254: U27.10 v1(53.34,15.24)
  ART03 w0.254: v1(13.72,23.17) 24.95,11.94 43.04,11.94 44.82,13.72 50.8,13.72 51.27,14.19 52.29,14.19 v1(53.34,15.24)
  BOTTOM w0.254: U28.10 v1(53.34,15.24) ; J1.2 12.45,23.87 13.15,23.17 v1(13.72,23.17) D35.1
Z10: length 71
  TOP w0.254: D51.1 v1(143.51,40.33) 148.2,40.33 J2.9 ; U47.10 v1(113.67,15.24)
  ART03 w0.254: v1(143.51,40.33) 144.27,39.56 144.27,38.35 145.36,37.26 145.36,25.58 145.67,25.27 145.67,19.05 141.53,14.91 137.11,14.91 135.89,16.13 121.58,16.13 120.09,14.63 114.27,14.63 v1(113.67,15.24)
  BOTTOM w0.254: U48.10 v1(113.67,15.24)
Z11: length 144.3
  TOP w0.254: v1(131.83,18.03) 130.56,19.3 129.43,19.3 125.35,23.39 125.35,34.8 124.59,35.56 116.22,35.56 115.44,36.33 115.44,53.47 109.73,59.18 101.87,59.18 101.24,58.55 R200.2 ; R210.2 129.54,10.81 v1(129.54,9.91) ; D54.1 v1(143.51,53.03) 147.26,53.03 147.87,53.64 J2.4
  ART03 w0.254: v1(143.51,53.03) 147.93,48.61 147.93,18.26 141.05,11.38 132.12,11.38 131.2,10.46 130.1,10.46 v1(129.54,9.91)
  ART04 w0.254: v1(129.54,9.91) 130.18,10.54 130.18,18.29 130.56,18.67 131.19,18.67 v1(131.83,18.03)
Z_SWITCH: length 31
  TOP w0.254: v1(144.15,33.33) D16.1 146.49,33.33 147.36,34.21 150.92,34.21 152.63,35.91 J2.27 ; U7.10 v1(138.43,18.03)
  ART03 w0.254: v1(144.15,33.33) 143.51,32.7 143.51,27.94 142.49,26.92 142.49,19.94 139.95,17.4 139.06,17.4 v1(138.43,18.03)
N1072360: length 6.5
  TOP w0.254: v1(76.07,40.01) 75.98,39.91 U6.13
  BOTTOM w0.381: FB3.1 76.71,43.05 76.96,42.8 C36.1 C35.1 C34.1 v1(76.07,40.01)
N1089979: length 26.8
  TOP w0.152: v1(79.76,27.43) 80.32,28 SW1.1 81.21,28 81.92,28.7 84.45,28.7 85.16,28 SW1.2 v1(86.29,28) ; v1(76.07,42.55) 75.7,42.91 U6.7
  ART04 w0.127: v1(79.76,27.43) 78.36,28.83 78.36,37.59 77.6,38.35 77.6,41.02 v1(76.07,42.55)
  BOTTOM w0.152: C32.1 86.16,28 v1(86.29,28)
N1090446: length 5.5
  TOP w0.152: Y1.1 69.55,43.94 C31.1 72.64,43.94 73.17,43.41 U6.6
N1090465: length 6
  TOP w0.152: U6.5 73.31,43.91 C30.1 69.55,45.47 Y1.2
N1090963: length 24
  TOP w0.152: R38.1 v1(78.11,50.42) 78.26,50.26 U6.60 ; J9.1 v1(74.93,67.06)
  ART04 w0.127: v1(74.93,67.06) 77.47,64.52 77.47,51.05 v1(78.11,50.42)
N1093241: length 2.6
  TOP w0.152: U6.42 87.01,42.91 v1(87.12,42.8)
  BOTTOM w0.152: R36.1 v1(87.12,42.8)
N1098241: length 11.6
  TOP w0.152: U6.8 72.77,42.41 v1(71.63,41.27) 70.74,41.27 ; v1(66.29,41.27) 65.91,40.89 D9.3
  BOTTOM w0.152: v1(71.63,41.27) 70.74,41.27 70.74,40.89 70.48,40.64 66.93,40.64 v1(66.29,41.27)
N1098327: length 14.5
  TOP w0.152: 70.74,40.01 v1(71.63,40.01) 71.63,40.51 73.03,41.91 U6.9
  BOTTOM w0.152: D10.3 65.41,40.89 66.93,39.37 70.48,39.37 70.74,39.62 70.74,40.01 v1(71.63,40.01)
N1119775: length 4.8
  TOP w0.152: U6.20 77.76,34.96 76.71,33.91 76.07,33.91 R28.2
N1119777: length 4.1
  TOP w0.152: R29.2 78.26,34.83 U6.21
N1119779: length 3.4
  TOP w0.152: R34.2 79.12,33.77 79.26,33.91 U6.23
N1119811: length 3.6
  TOP w0.152: R41.1 81.92,50.67 81.76,50.52 U6.53
N1122591: length 3.8
  TOP w0.152: R33.2 77.85,33.78 78.76,34.69 U6.22
N1152179: length 3.7
  TOP w0.152: U6.51 82.76,50.25 83.19,50.67 R40.2
N2171352: length 6.2
  BOTTOM w0.381: R5.2 R8.1 41.27,78.99 41.78,78.49 43.86,78.49 U1.6
N2171362: length 5.2
  BOTTOM w0.381: U1.7 45,77 45.47,77.47 45.47,78.49 45.09,78.87 C9.1 R4.2
N2171370: length 1.3
  BOTTOM w0.381: R4.1 C8.1
N2171378: length 2.2
  BOTTOM w0.381: C10.1 39.37,77.6 39.97,77 U1.4
N2171394: length 2.4
  BOTTOM w0.381: R7.1 39.24,78.87 40.31,77.8 U1.5
N2171436: length 3.6
  BOTTOM w0.381: 45.47,73.41 45.09,73.03 43.05,73.03 ; U1.9 45.55,75.4
N2171440: length 2.9
  BOTTOM w0.381: C2.1 40.9,73.03 40.55,73.38 U1.1
N2172060: length 1.4
  TOP w0.381: R6.2 D3.1
N2174013: length 2.1
  TOP w0.254: U2.9 61.72,77.33 61.61,77.22 60.83,77.22
N2174285: length 2.2
  TOP w0.254: U2.4 66.28,77.33 67.06,78.11 R9.1
N2324503: length 2.6
  TOP w0.381: C23.2 109.6,67.82 v1(109.73,67.94)
  BOTTOM w0.254: U4.3 v1(109.73,67.94)
N2324571: length 3
  TOP w0.381: v1(109.73,69.22) 109.6,69.34 C23.1
  BOTTOM w0.254: U4.2 109.09,68.45 109.73,69.09 v1(109.73,69.22)
N2324798: length 7.6
  TOP w0.381: v1(102.36,67.44) 101.73,68.07 101.73,69.85 v1(102.36,70.48)
  BOTTOM w0.254: v1(102.36,67.44) 102.87,67.94 U4.8
  BOTTOM w0.381: R18.2 R20.1 v1(102.36,70.48)
N2325202: length 2.9
  TOP w0.381: v1(102.36,69.47) 102.62,69.22 R19.1
  BOTTOM w0.254: U4.10 102.89,68.94 v1(102.36,69.47)
N2325262: length 1.3
  TOP w0.381: C27.1 R17.2
N2325279: length 2.8
  TOP w0.381: R17.1 102.87,67.94 v1(102.36,68.45)
  BOTTOM w0.254: U4.9 102.37,68.45 v1(102.36,68.45)
N2325487: length 3.9
  BOTTOM w0.254: 109.47,67.18 109.21,67.44 U4.4
  BOTTOM w0.381: R16.1 107.44,63.63 107.71,63.36 109.35,63.36
N2326478: length 3.5
  BOTTOM w0.254: C25.2 108.84,65.79 108.84,66.8 108.7,66.95 U4.5
  BOTTOM w0.381: C25.2 R16.2
N2327690: length 3.4
  TOP w0.381: C15.2 38.1,61.98 v1(38.86,61.21)
  BOTTOM w0.254: U3.3 38.73,61.34 v1(38.86,61.21)
N2327718: length 3.9
  TOP w0.381: v1(40.13,61.21) 39.62,61.72 C15.1
  BOTTOM w0.254: v1(40.13,61.21) 39.75,61.21 39.24,61.73 U3.2
N2327760: length 3.7
  BOTTOM w0.254: U3.8 R12.2
  BOTTOM w0.381: R12.2 R15.1
N2327816: length 4.6
  BOTTOM w0.254: R14.1 42.55,68.71 41.66,67.82 40.01,67.82 39.73,67.55 U3.10
N2327844: length 1.3
  BOTTOM w0.381: R11.2 C22.1
N2327848: length 2.7
  BOTTOM w0.254: R11.1 40.01,68.58 39.24,67.81 U3.9
N2332877: length 3.6
  TOP w0.254: R23.1 65.15,59.18 v1(65.91,58.42)
  BOTTOM w0.254: U5.10 65.68,58.66 v1(65.91,58.42)
N2333047: length 2.9
  TOP w0.381: C28.1 66.55,59.05 v1(67.18,58.42)
  BOTTOM w0.254: v1(67.18,58.42) 67.18,58.43 U5.7
N2333053: length 1.4
  TOP w0.381: C28.2 68.07,58.8 v1(68.45,58.42)
N2334537: length 1.4
  TOP w0.381: R13.2 D6.1
N2348416: length 14.5
  TOP w0.152: U6.14 72.69,39.41 72.26,38.99 72.26,38.1 v1(71.63,37.47) 70.74,37.47
  BOTTOM w0.152: D13.3 66.29,37.72 67.18,36.83 70.48,36.83 70.74,37.08 70.74,37.47 v1(71.63,37.47)
N2348424: length 12.9
  TOP w0.152: U6.11 72.79,40.91 72.26,40.39 72.26,39.88 71.63,39.24 v1(71.63,38.73) 70.74,38.73 ; D14.3 65.28,37.72 v1(66.29,38.73)
  BOTTOM w0.152: v1(66.29,38.73) 66.93,38.1 70.48,38.1 70.74,38.35 70.74,38.73 v1(71.63,38.73)
N2355333: length 8
  TOP w0.152: U6.57 79.76,50.04 80.64,50.93 R42.1 80.26,51.31 80.01,51.56 80.01,53.98 80.58,54.54 Q1.1
N2356046: length 8
  TOP w0.152: U6.58 79.26,50.43 79.38,50.55 R43.1 78.99,51.31 78.74,51.56 78.74,53.34 77.4,54.68 Q2.1
N2358793: length 19.3
  TOP w0.152: U8.6 64.05,18.71 v1(64.39,19.05)
  BOTTOM w0.152: v1(64.39,19.05) 67.44,16 74.17,16 74.42,16.26 R48.1 75.06,17.4 75.95,17.4 76.2,17.14 J8.2
N2358897: length 1.6
  TOP w0.305: 68.96,19.36 70.54,19.36
N2359035: length 5.6
  TOP w0.152: C47.1 v1(66.67,15.11) 66.55,15.24 C48.2 68.08,17.41 68.96,17.41
  BOTTOM w0.152: C47.1 v1(66.67,15.11)
N2359039: length 5.6
  TOP w0.152: U8.8 64,17.41 C48.1 65.53,15.24 v1(65.41,15.11) C49.1
  BOTTOM w0.152: C49.1 v1(65.41,15.11)
N2359131: length 21.1
  TOP w0.152: v1(67.94,12.32) 71.5,15.88 75.44,15.88 75.95,16.38 75.95,17.4 v1(75.31,18.03)
  BOTTOM w0.152: R51.1 R47.1 v1(75.31,18.03) 76.45,18.03 78.11,19.68 J8.1 ; R50.1 67.56,13.21 67.94,12.83 v1(67.94,12.32)
N2359257: length 5.7
  TOP w0.152: 68.96,18.71 69.94,18.71 70.74,17.91 C43.2 72.39,17.91 v1(72.52,18.03) C42.1
  BOTTOM w0.152: C42.1 v1(72.52,18.03)
N2359261: length 5.9
  TOP w0.152: 68.96,18.06 69.95,18.06 71.12,16.89 C43.1 72.39,16.89 v1(72.52,16.76) C46.1
  BOTTOM w0.152: C46.1 v1(72.52,16.76)
N2361859: length 2.1
  TOP w0.254: C55.1 91.2,37.47 91.31,37.58 U9.9
N2362117: length 2.3
  TOP w0.254: U9.4 95.87,37.58 96.77,38.48 R53.1
N2363053: length 2.6
  TOP w0.381: C56.2 94.36,67.82 v1(94.49,67.94)
  BOTTOM w0.254: U10.3 v1(94.49,67.94)
N2363081: length 3
  TOP w0.381: C56.1 94.36,69.34 v1(94.49,69.22)
  BOTTOM w0.254: U10.2 93.85,68.45 94.49,69.09 v1(94.49,69.22)
N2363123: length 7.6
  TOP w0.381: v1(87.12,67.44) 86.49,68.07 86.49,69.85 v1(87.12,70.48)
  BOTTOM w0.254: U10.8 87.63,67.94 v1(87.12,67.44)
  BOTTOM w0.381: R56.2 R58.1 v1(87.12,70.48)
N2363179: length 2.9
  TOP w0.381: v1(87.12,69.47) 87.38,69.22 R57.1
  BOTTOM w0.254: v1(87.12,69.47) 87.65,68.94 U10.10
N2363207: length 1.3
  TOP w0.381: C58.1 R55.2
N2363211: length 2.8
  TOP w0.381: v1(87.12,68.45) 87.63,67.94 R55.1
  BOTTOM w0.254: U10.9 87.13,68.45 v1(87.12,68.45)
N2363241: length 3.9
  BOTTOM w0.254: 94.23,67.18 93.97,67.44 U10.4
  BOTTOM w0.381: R54.1 92.2,63.63 92.47,63.36 94.11,63.36
N2363393: length 3.5
  BOTTOM w0.254: U10.5 93.46,66.95 93.6,66.8 93.6,65.79 C59.2
  BOTTOM w0.381: C59.2 R54.2
N2365789: length 9.1
  TOP w0.381: R151.1 U43.5 57.15,62.99 56.88,62.72 53.61,62.72 53.34,62.99 U43.8
N2365809: length 6.3
  TOP w0.381: U43.4 v1(57.15,57.4) ; U43.3 v1(55.88,57.4)
  BOTTOM w0.381: v1(55.88,57.4) R153.2 R152.1 v1(57.15,57.4)
N2368555: length 8.4
  TOP w0.381: U45.5 100.97,17.91 100.2,17.14 97.92,17.14 97.16,17.91 U45.8 v1(97.16,20.07)
  BOTTOM w0.381: R154.1 v1(97.16,20.07)
N2368583: length 6.3
  TOP w0.152: U45.4 v1(100.97,11.68) ; v1(99.69,11.68) U45.3
  BOTTOM w0.152: v1(99.69,11.68) R156.2 R155.1 v1(100.97,11.68)
N2372492: length 8.7
  TOP w0.152: C194.2 72.14,63.5 71.75,63.12 71.75,61.85 72.01,61.59 74.8,61.59 75.76,62.56 U41.4
N2372496: length 3.1
  TOP w0.152: C194.1 75.31,63.5 75.67,63.86 U41.2
N2372506: length 3.3
  TOP w0.152: U41.3 75.78,63.21 74.8,62.23 C197.1
N2372514: length 3.3
  TOP w0.152: U41.7 75.72,60.6 74.8,59.69 C196.1
N2372518: length 4.8
  TOP w0.152: C195.2 73.15,60.58 73.41,60.33 74.8,60.33 75.73,61.25 U41.6
N2372530: length 3.3
  TOP w0.152: C195.1 74.8,60.96 75.75,61.9 U41.5
N2372534: length 2.4
  TOP w0.152: v1(81.53,61.59) 81.73,61.59 82.04,61.9 U41.12
  BOTTOM w0.152: R143.2 v1(81.53,61.59)
N2372542: length 2.4
  TOP w0.152: v1(81.53,64.14) 81.9,64.51 U41.16
  BOTTOM w0.152: R144.2 v1(81.53,64.14)
N2372558: length 3
  TOP w0.152: R146.1 75.43,64.77 75.69,64.51 U41.1
N2372642: length 2.4
  TOP w0.152: U41.9 81.9,59.95 v1(81.53,60.33)
  BOTTOM w0.152: R145.2 v1(81.53,60.33)
N2373113: length 2.9
  TOP w0.152: U42.4 89.84,16.33 89.28,16.89 v1(88.9,16.89)
  BOTTOM w0.152: C199.2 v1(88.9,16.89)
N2373117: length 2.4
  TOP w0.152: U42.2 88.54,14.45 v1(88.9,14.1)
  BOTTOM w0.152: C199.1 v1(88.9,14.1)
N2373127: length 2.9
  TOP w0.152: v1(90.17,14.1) 89.79,14.1 89.19,14.69 U42.3
  BOTTOM w0.152: C202.1 v1(90.17,14.1)
N2373135: length 3
  TOP w0.152: v1(92.71,14.1) 92.2,14.1 91.8,14.5 U42.7
  BOTTOM w0.152: C201.1 v1(92.71,14.1)
N2373139: length 2.4
  TOP w0.152: v1(91.44,16.89) 91.15,16.6 U42.6
  BOTTOM w0.152: C200.2 v1(91.44,16.89)
N2373151: length 2.9
  TOP w0.152: U42.5 90.5,14.66 91.06,14.1 v1(91.44,14.1)
  BOTTOM w0.152: C200.1 v1(91.44,14.1)
N2373155: length 3
  TOP w0.152: R148.2 90.81,23.5 90.5,23.19 U42.12
N2373163: length 3.1
  TOP w0.152: U42.16 87.89,23.11 88.27,23.48 R147.2
N2373179: length 2.4
  TOP w0.152: v1(87.63,14.1) 87.89,14.36 U42.1
  BOTTOM w0.152: R150.1 v1(87.63,14.1)
N2373263: length 3.1
  TOP w0.152: U42.9 92.45,22.62 92.08,22.99 R149.2
N2407837: length 2.9
  TOP w0.152: U33.4 R123.2
N2407841: length 3.4
  TOP w0.152: U33.5 122.05,29.21 121.41,29.84 120.52,29.84 R125.1
N2408507: length 2.9
  BOTTOM w0.152: R126.2 U34.4
N2408511: length 3.4
  BOTTOM w0.152: R127.1 120.52,28.57 121.41,28.57 122.05,27.94 U34.5
N2410769: length 2.9
  BOTTOM w0.152: R128.2 U35.4
N2410773: length 3.4
  BOTTOM w0.152: U35.5 122.05,71.75 121.41,72.39 120.52,72.39 R130.1
N2411439: length 2.9
  TOP w0.152: U36.4 R131.2
N2411443: length 3.4
  TOP w0.152: U36.5 122.05,73.03 121.41,73.66 120.52,73.66 R132.1
N2413701: length 2.9
  TOP w0.152: U37.4 R133.2
N2413705: length 3.4
  TOP w0.152: R135.1 120.52,44.45 121.41,44.45 122.05,43.81 U37.5
N2414371: length 2.9
  BOTTOM w0.152: R136.2 U38.4
N2414375: length 3.4
  BOTTOM w0.152: R137.1 120.52,43.18 121.41,43.18 122.05,42.55 U38.5
N2416633: length 2.9
  TOP w0.152: U39.4 R138.2
N2416637: length 3.4
  TOP w0.152: U39.5 122.05,58.42 121.41,59.05 120.52,59.05 R140.1
N2417303: length 2.9
  BOTTOM w0.152: R141.2 U40.4
N2417307: length 3.4
  BOTTOM w0.152: R142.1 120.52,57.78 121.41,57.78 122.05,57.15 U40.5
N2487119: length 21.8
  TOP w0.254: R175.1 122.3,18.29 121.92,17.91 U49.12 v1(121.92,14.35)
  ART03 w0.254: v1(121.92,14.35) 123.57,12.7 130.43,12.7 v1(132.08,14.35)
  BOTTOM w0.152: v1(121.92,14.35) U50.12
  BOTTOM w0.254: v1(132.08,14.35) 132.08,14.08 R208.1
N2487163: length 12.3
  TOP w0.254: U49.10 v1(124.46,14.35) ; v1(129.54,14.35) 129.54,13.32 R210.1
  ART03 w0.254: v1(124.46,14.35) 125.09,13.72 128.91,13.72 v1(129.54,14.35)
  BOTTOM w0.254: U50.10 v1(124.46,14.35)
N2487167: length 19.1
  TOP w0.254: R175.2 125.09,19.46 123.83,18.19 123.83,17.78 123.19,17.14 U49.11 v1(123.19,14.35) ; v1(130.81,14.35) 130.81,13.32 R209.1
  ART03 w0.254: v1(130.81,14.35) 129.67,13.21 124.33,13.21 v1(123.19,14.35)
  BOTTOM w0.254: U50.11 v1(123.19,14.35)
N2487191: length 9.6
  TOP w0.254: v1(125.73,14.35) U49.9
  ART03 w0.254: v1(128.27,14.35) v1(125.73,14.35)
  BOTTOM w0.254: R211.1 128.27,14.08 v1(128.27,14.35) ; U50.9 v1(125.73,14.35)
N2496895: length 2.4
  TOP w0.152: U51.4 103.18,31.31 103.5,30.99 C217.2
N2496899: length 7.7
  TOP w0.152: C217.1 103.5,28.45 103,27.94 101.85,27.94 101.6,28.19 101.6,30.96 101.88,31.24 U51.2
N2496903: length 2.7
  TOP w0.152: U51.7 105.13,31.78 106.05,30.86 C215.1
N2496907: length 2.4
  TOP w0.152: C219.1 102.23,30.99 102.53,31.28 U51.3
N2496915: length 11.3
  TOP w0.152: v1(104.78,39.88) 104.48,39.58 U51.11 104.48,37.47 104.73,37.21 106.17,37.21 107.48,38.52 Q6.3 Q4.3
  BOTTOM w0.152: v1(104.78,39.88) 104.78,40.77
N2496923: length 4.2
  TOP w0.152: U51.6 104.48,31.66 105.41,30.73 105.41,29.59 105.16,29.34 C218.2
N2496931: length 2.7
  TOP w0.152: C218.1 103.83,31.3 U51.5
N2496939: length 2.7
  TOP w0.152: 104.78,40.77 103.83,39.82 U51.12
N2496947: length 2.9
  TOP w0.152: 99.69,40.77 101.23,39.23 U51.16
N2496959: length 2.4
  TOP w0.152: R177.1 100.97,30.99 101.23,31.25 U51.1
N2497023: length 2.4
  TOP w0.152: 106.05,40.77 105.78,40.5 U51.9
N2498167: length 2.5
  TOP w0.152: R186.2 R185.2 R180.1
N2498410: length 4.2
  TOP w0.152: Q3.3 110.8,35.66 Q4.1 v1(110.8,37.47)
  BOTTOM w0.152: R187.1 111.25,37.02 v1(110.8,37.47)
